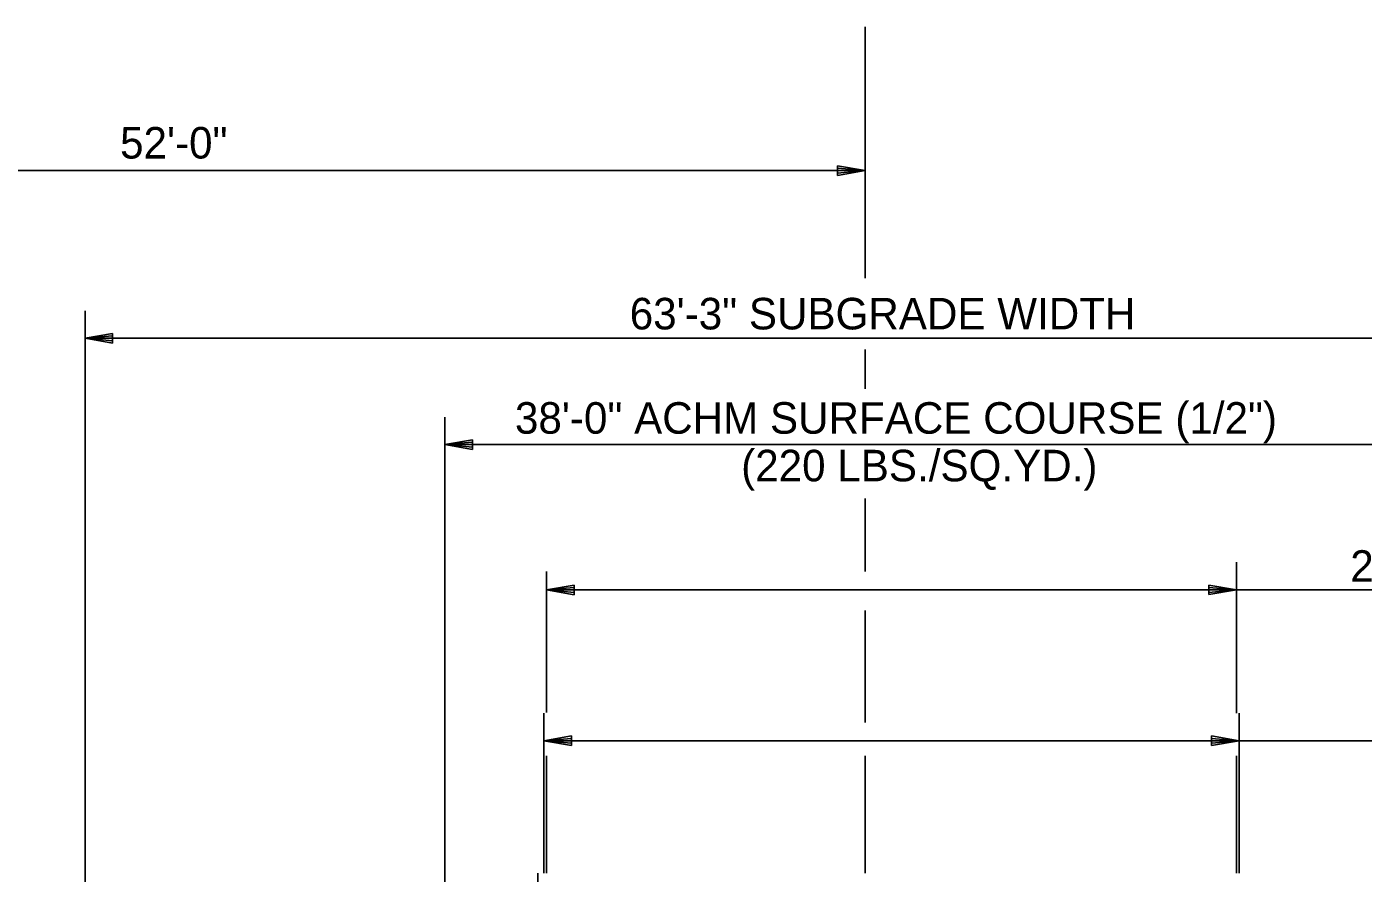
# Model space of a CAD drawing. Extents: x 1734743 to 1735935, y 759845 to 763831.
# Drawn here: x 1735773.2 to 1735824.1, y 763702.9 to 763735.1 of the extents above; entities that cross this region are included whole.
import ezdxf

# ---------------------------------------------------------------- set-up
doc = ezdxf.new("R2010")
doc.units = 0
doc.layers.add('19', color=7, linetype='Continuous')

msp = doc.modelspace()

# ---------------------------------------------------------------- linework, layer by layer
at = {"layer": '19'}
for p, q in [((1735805.144, 763725.493), (1735805.144, 763735.056)), ((1735804.094, 763729.769), (1735804.094, 763729.402)), ((1735805.144, 763729.586), (1735804.094, 763729.769)), ((1735805.144, 763729.586), (1735753.144, 763729.586)), ((1735804.864, 763729.612), (1735804.094, 763729.673)), ((1735804.094, 763729.402), (1735805.144, 763729.586)), ((1735804.094, 763729.489), (1735804.864, 763729.559)), ((1735775.459, 763701.353), (1735775.459, 763724.25)), ((1735776.509, 763723.388), (1735775.459, 763723.204)), ((1735775.459, 763723.204), (1735838.547, 763723.204)), ((1735775.459, 763723.204), (1735776.509, 763723.02)), ((1735776.509, 763723.291), (1735775.739, 763723.23)), ((1735775.739, 763723.178), (1735776.509, 763723.108)), ((1735776.509, 763723.02), (1735776.509, 763723.388)), ((1735805.144, 763721.276), (1735805.144, 763722.78)), ((1735789.147, 763698.761), (1735789.147, 763720.208)), ((1735790.197, 763719.346), (1735789.147, 763719.162)), ((1735827.144, 763719.166), (1735789.147, 763719.162)), ((1735789.147, 763719.162), (1735790.197, 763718.978)), ((1735790.197, 763719.249), (1735789.427, 763719.188)), ((1735789.427, 763719.136), (1735790.197, 763719.066)), ((1735790.197, 763718.978), (1735790.197, 763719.346)), ((1735805.144, 763714.332), (1735805.144, 763717.102)), ((1735819.271, 763708.943), (1735819.271, 763714.683)), ((1735793.019, 763708.968), (1735793.019, 763714.332)), ((1735794.069, 763713.817), (1735793.019, 763713.633)), ((1735793.019, 763713.633), (1735794.069, 763713.449)), ((1735856.932, 763713.633), (1735793.019, 763713.633)), ((1735794.069, 763713.721), (1735793.299, 763713.659)), ((1735793.299, 763713.607), (1735794.069, 763713.537)), ((1735794.069, 763713.449), (1735794.069, 763713.817)), ((1735818.221, 763713.817), (1735818.221, 763713.45)), ((1735819.271, 763713.633), (1735818.221, 763713.817)), ((1735818.991, 763713.659), (1735818.221, 763713.721)), ((1735818.221, 763713.45), (1735819.271, 763713.633)), ((1735818.221, 763713.537), (1735818.991, 763713.607)), ((1735805.144, 763708.591), (1735805.144, 763712.847)), ((1735792.917, 763702.851), (1735792.917, 763708.943)), ((1735819.376, 763702.851), (1735819.376, 763708.943)), ((1735857.034, 763707.893), (1735792.913, 763707.893)), ((1735793.967, 763708.076), (1735792.917, 763707.893)), ((1735792.917, 763707.893), (1735793.967, 763707.709)), ((1735793.967, 763707.98), (1735793.197, 763707.919)), ((1735793.197, 763707.866), (1735793.967, 763707.796)), ((1735793.967, 763707.709), (1735793.967, 763708.076)), ((1735818.326, 763708.076), (1735818.326, 763707.709)), ((1735819.376, 763707.893), (1735818.326, 763708.076)), ((1735819.096, 763707.919), (1735818.326, 763707.98)), ((1735818.326, 763707.709), (1735819.376, 763707.893)), ((1735818.326, 763707.796), (1735819.096, 763707.866)), ((1735793.019, 763702.851), (1735793.019, 763707.313)), ((1735805.144, 763702.851), (1735805.144, 763707.313)), ((1735819.271, 763702.851), (1735819.271, 763707.313)), ((1735792.69, 763698.761), (1735792.69, 763702.851))]:
    msp.add_line(p, q, dxfattribs=at)

# ---------------------------------------------------------------- texts
for s, p in [('52\'-0"', (1735776.791, 763730.042)), ('63\'-3" SUBGRADE WIDTH', (1735796.184, 763723.541)), ('38\'-0" ACHM SURFACE COURSE (1/2")', (1735791.817, 763719.573)), ('(220 LBS./SQ.YD.)', (1735800.425, 763717.761)), ('26\'-3" ACHM SURFACE COURSE (1/2")', (1735823.603, 763713.939))]:
    msp.add_text(s, height=1.2, dxfattribs=at).set_placement(p)

doc.saveas('drawing.dxf')
